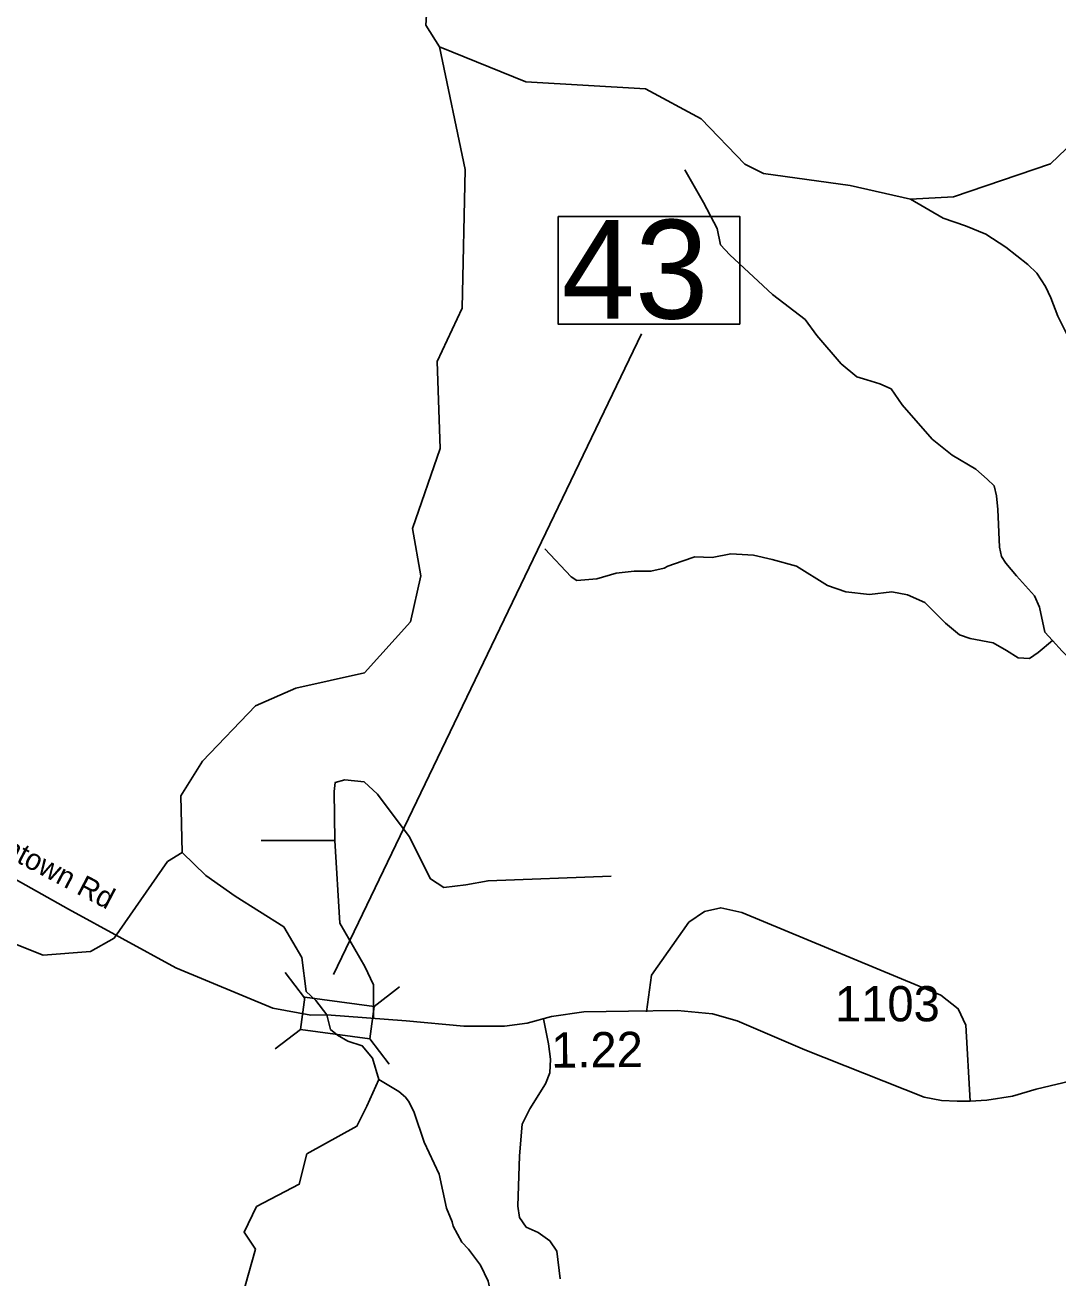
# Model space of a CAD drawing. Extents: x 1248224 to 1454986, y 825081 to 985870.
# Drawn here: x 1349562 to 1353225, y 860700 to 865144 of the extents above; entities that cross this region are included whole.
import ezdxf

# ---------------------------------------------------------------- set-up
doc = ezdxf.new("R2010")
doc.units = 0
for name, color, linetype in [('Exist Hydrographic Creek Single Shore', 7, 'Continuous'), ('Exist Hydrographic Misc Water Feature', 7, 'Continuous'), ('Exist Road Non-System Type 51', 7, 'Continuous'), ('Exist Road Secondary Mileage Hundredths English Label', 7, 'Continuous'), ('Exist Road Secondary Structure Standard Bridge CELL', 7, 'Continuous'), ('Exist Road Secondary Structure Standard Bridge Number Label', 7, 'Continuous'), ('Exist Road Secondary Type 10 Attributed', 7, 'Continuous'), ('Exist Road Secondary Type 51 Attributed', 7, 'Continuous'), ('Exist Road Secondary Type 51 Label', 7, 'Continuous'), ('Exist Road Secondary Type 51 Number Label', 7, 'Continuous')]:
    doc.layers.add(name, color=color, linetype=linetype)

msp = doc.modelspace()

# ---------------------------------------------------------------- linework, layer by layer
at = {"layer": 'Exist Hydrographic Creek Single Shore'}
for points in [[(1351031.3, 865067.3), (1351337.2, 864942.9), (1351762.3, 864917.9), (1351959.2, 864812.2), (1352114.3, 864651.5), (1352180.3, 864617.4), (1352488.3, 864575), (1352701.2, 864526.8), (1352854.3, 864534.9), (1353198.3, 864652.7), (1353309.3, 864758.9), (1353405.3, 864963.7), (1353564.3, 864960.5), (1353761.2, 864831.9), (1353937.3, 864887.3), (1354058.3, 865075.4), (1354650.3, 865454.1), (1355068.3, 865895.5), (1355224.3, 866141.8)], [(1351031.3, 865067.3), (1350983.2, 865143.7), (1350995.2, 865327.3)], [(1350118.3, 862209.9), (1350114.3, 862410.2), (1350191.3, 862533.3), (1350379.2, 862729.8), (1350522.2, 862792.6), (1350765.2, 862846.9), (1350928.2, 863027.4), (1350965.2, 863190.7), (1350935.2, 863358.9), (1351033.2, 863642.5), (1351023.3, 863951.2), (1351111.2, 864139.8), (1351122.2, 864632), (1351031.3, 865067.3)], [(1350632.1, 861633.8), (1350592.8, 861685), (1350559, 861717), (1350543.5, 861836.7), (1350479.8, 861945.6), (1350306.2, 862055.1), (1350202.8, 862128.4), (1350118.3, 862209.9)], [(1350010.2, 859554.6), (1350015.3, 859784.7), (1350342.3, 860672.3), (1350378.3, 860802.8), (1350338.3, 860862.8), (1350382.3, 860953.7), (1350534.2, 861032.8), (1350561.3, 861140.6), (1350738.3, 861238.7), (1350773.3, 861310.3), (1350816.1, 861404.3), (1350793.7, 861479.4), (1350757.2, 861524.2), (1350706.1, 861539.7), (1350669.5, 861561.6), (1350644.9, 861581.7), (1350632.1, 861633.8)]]:
    msp.add_lwpolyline(points, dxfattribs=at)
at = {"layer": 'Exist Hydrographic Misc Water Feature'}
for points in [[(1353256.6, 864047.5), (1353224.1, 864112.3), (1353199.5, 864176.9), (1353180.4, 864217.3), (1353149.5, 864264.1), (1353118.2, 864294.8), (1353039.6, 864356.7), (1352968.6, 864402.4), (1352897.2, 864432.1), (1352817.8, 864460), (1352701.2, 864526.8)], [(1343252.1, 861711), (1343773.1, 861858), (1344244.2, 862055.4), (1344470.1, 862109.9), (1344769.2, 862028.4), (1344958.1, 861932.7), (1345133.2, 861935.7), (1345929.2, 862093.7), (1346104.2, 862080.4), (1346502.2, 861980.5), (1346988.2, 862088.9), (1347872.2, 862451.9), (1348080.4, 862480.3), (1348305.2, 862459.6), (1348554.2, 862385.7), (1349295.2, 861976.8), (1349626.3, 861845.5), (1349793.3, 861858.5), (1349877.2, 861906.1), (1350067.2, 862178.1), (1350118.3, 862209.9)], [(1351511.8, 860340.9), (1351387.2, 860478.5), (1351340.2, 860521.7), (1351298.9, 860552.6), (1351247.9, 860599.8), (1351234.3, 860616.2), (1351211.2, 860656.7), (1351203.9, 860688.9), (1351177.2, 860745.5), (1351134.5, 860802.5), (1351111, 860827.1), (1351080.3, 860883.8), (1351076.7, 860899.9), (1351055.8, 860948.4), (1351030.6, 861069), (1350977, 861182.3), (1350941.5, 861287), (1350924.2, 861323.4), (1350910.7, 861341.8), (1350887.1, 861362.3), (1350816.1, 861404.3)]]:
    msp.add_lwpolyline(points, dxfattribs=at)
at = {"layer": 'Exist Road Non-System Type 51'}
msp.add_line((1350660.7, 862252.6), (1350398.6, 862252.3), dxfattribs=at)
for points in [[(1353178.6, 862991.1), (1353159.5, 863080.2), (1353141.8, 863120.1), (1353077.6, 863190.9), (1353040, 863235.2), (1353024.5, 863259.6), (1353017.9, 863292.8), (1353011.2, 863425.7), (1353006.8, 863474.4), (1352997.9, 863509.9), (1352973.6, 863534.2), (1352933.8, 863569.7), (1352849.7, 863618.4), (1352778.8, 863676), (1352672.6, 863797.8), (1352633.1, 863854.5), (1352593.3, 863872.2), (1352546.8, 863885.5), (1352511.4, 863896.6), (1352456, 863943.1), (1352369.7, 864042.8), (1352327.7, 864100.4), (1352212.6, 864189), (1352060.5, 864329.5), (1352027.3, 864365), (1352016.2, 864422.5), (1351967.5, 864515.6), (1351901.1, 864630.7)], [(1351405.2, 863286.8), (1351498.1, 863187.1), (1351518, 863173.8), (1351588.8, 863180.5), (1351657.5, 863200.4), (1351721.6, 863207), (1351781.4, 863207), (1351827.9, 863218.1), (1351841.2, 863224.8), (1351892.1, 863242.5), (1351936.3, 863258), (1351998.3, 863255.8), (1352064.7, 863269.1), (1352144.4, 863264.6), (1352210.8, 863249.1), (1352297.1, 863224.8), (1352407.7, 863156.1), (1352471.9, 863134), (1352556, 863125.1), (1352635.7, 863134), (1352691, 863122.9), (1352753, 863096.3), (1352826, 863023.2), (1352875.7, 862981.4), (1352913.3, 862968.1), (1352995.2, 862952.6), (1353041.7, 862926), (1353083.7, 862899.5), (1353123.5, 862897.2), (1353154.5, 862919.4), (1353205.4, 862961.5)], [(1350660.7, 862252.6), (1350657.9, 862426.4), (1350661.3, 862457.2), (1350695.4, 862467.4), (1350763.6, 862460.6), (1350811.4, 862416.2), (1350923.9, 862266), (1350999, 862115.8), (1351046.7, 862085.1), (1351125.2, 862095.3), (1351203.7, 862109), (1351640.3, 862126)], [(1350797.1, 861621), (1350797.1, 861740.5), (1350766.4, 861805.4), (1350677.7, 861959), (1350660.7, 862252.6)], [(1352913.3, 861328), (1352898.4, 861597.1), (1352871.1, 861655.2), (1352809.7, 861702.9), (1352103.6, 861996.5), (1352028.6, 862013.6), (1351970.6, 861999.9), (1351916, 861962.4), (1351783, 861774.6), (1351765.9, 861644.9)], [(1351400.4, 861619.1), (1351417.5, 861530.8), (1351424.9, 861476.8), (1351422.4, 861427.8), (1351407.7, 861388.6), (1351351.4, 861300.3), (1351324.4, 861246.4), (1351314.6, 861133.6), (1351309.7, 860954.6), (1351314.6, 860915.3), (1351339.1, 860881), (1351380.8, 860861.4), (1351422.4, 860832), (1351446.9, 860795.2), (1351459.2, 860697.1)]]:
    msp.add_lwpolyline(points, dxfattribs=at)
at = {"layer": 'Exist Road Secondary Structure Standard Bridge CELL'}
for p, q in [((1350553.1, 861694.4), (1350484.4, 861784.3)), ((1350889, 861732.5), (1350799.1, 861663.7)), ((1350538.2, 861582.2), (1350448.3, 861513.4)), ((1350852.6, 861459), (1350783.8, 861548.9))]:
    msp.add_line(p, q, dxfattribs=at)
msp.add_lwpolyline([(1350783.8, 861548.9), (1350538.1, 861581.7), (1350553.4, 861696.4), (1350799.1, 861663.7)], close=True, dxfattribs=at)
at = {"layer": 'Exist Road Secondary Structure Standard Bridge Number Label'}
msp.add_line((1350655.5, 861776.7), (1351747.8, 864049.4), dxfattribs=at)
msp.add_lwpolyline([(1351451.8, 864465.9), (1352095.9, 864465.9), (1352095.9, 864083.6), (1351451.8, 864083.6)], close=True, dxfattribs=at)
at = {"layer": 'Exist Road Secondary Type 10 Attributed'}
msp.add_lwpolyline([(1354138.1, 862639.6), (1354066.8, 862659.2), (1353959, 862667), (1353912.1, 862662.3), (1353851.1, 862659.2), (1353807.4, 862662.3), (1353746.4, 862681.1), (1353627.7, 862731.1), (1353565.2, 862748.3), (1353532.3, 862751.5), (1353477.7, 862760.8), (1353408.9, 862774.9), (1353362, 862804.6), (1353291.7, 862870.3), (1353240.1, 862923.5), (1353205.4, 862961.5), (1353178.6, 862991.1)], dxfattribs=at)
at = {"layer": 'Exist Road Secondary Type 51 Attributed'}
for points in [[(1350632.1, 861633.8), (1350575.5, 861632.5), (1350440.6, 861656.9), (1350095.8, 861800.6), (1349715.8, 862008.2), (1349431, 862167.6), (1349312.2, 862227.1), (1349215, 862260.8), (1349127.3, 862268.9), (1349038.2, 862275.7), (1348999.1, 862286.5), (1348909.2, 862332.9), (1348779.6, 862411.3), (1348508.3, 862649), (1348286.9, 862840.9)], [(1353723.8, 861507.3), (1353146.8, 861369.8), (1353063.1, 861345.5), (1352972.7, 861330.7), (1352913.3, 861328), (1352867.4, 861328), (1352812.1, 861329.3), (1352749.6, 861341.1), (1352327.1, 861509.9), (1352086.8, 861612.6), (1351999.9, 861636.8), (1351875.7, 861649), (1351701.6, 861646.3), (1351543.6, 861644.9), (1351428.9, 861627.4), (1351342.5, 861604.4), (1351261.5, 861593.6), (1351118.1, 861593.4), (1350913, 861612.3), (1350632.1, 861633.8)]]:
    msp.add_lwpolyline(points, dxfattribs=at)

# ---------------------------------------------------------------- texts
at = {"layer": 'Exist Road Secondary Mileage Hundredths English Label'}
msp.add_text('1.22', height=125, rotation=0.4901, dxfattribs=at).set_placement((1351427.7, 861446))
at = {"layer": 'Exist Road Secondary Structure Standard Bridge Number Label'}
msp.add_text('43', height=350, dxfattribs=at).set_placement((1351464.3, 864103.4))
at = {"layer": 'Exist Road Secondary Type 51 Label'}
msp.add_text('Germantown Rd', height=75, rotation=332.3678, dxfattribs=at).set_placement((1349206.7, 862344.8))
at = {"layer": 'Exist Road Secondary Type 51 Number Label'}
msp.add_text('1103', height=125, dxfattribs=at).set_placement((1352433.8, 861610.6))

doc.saveas('drawing.dxf')
